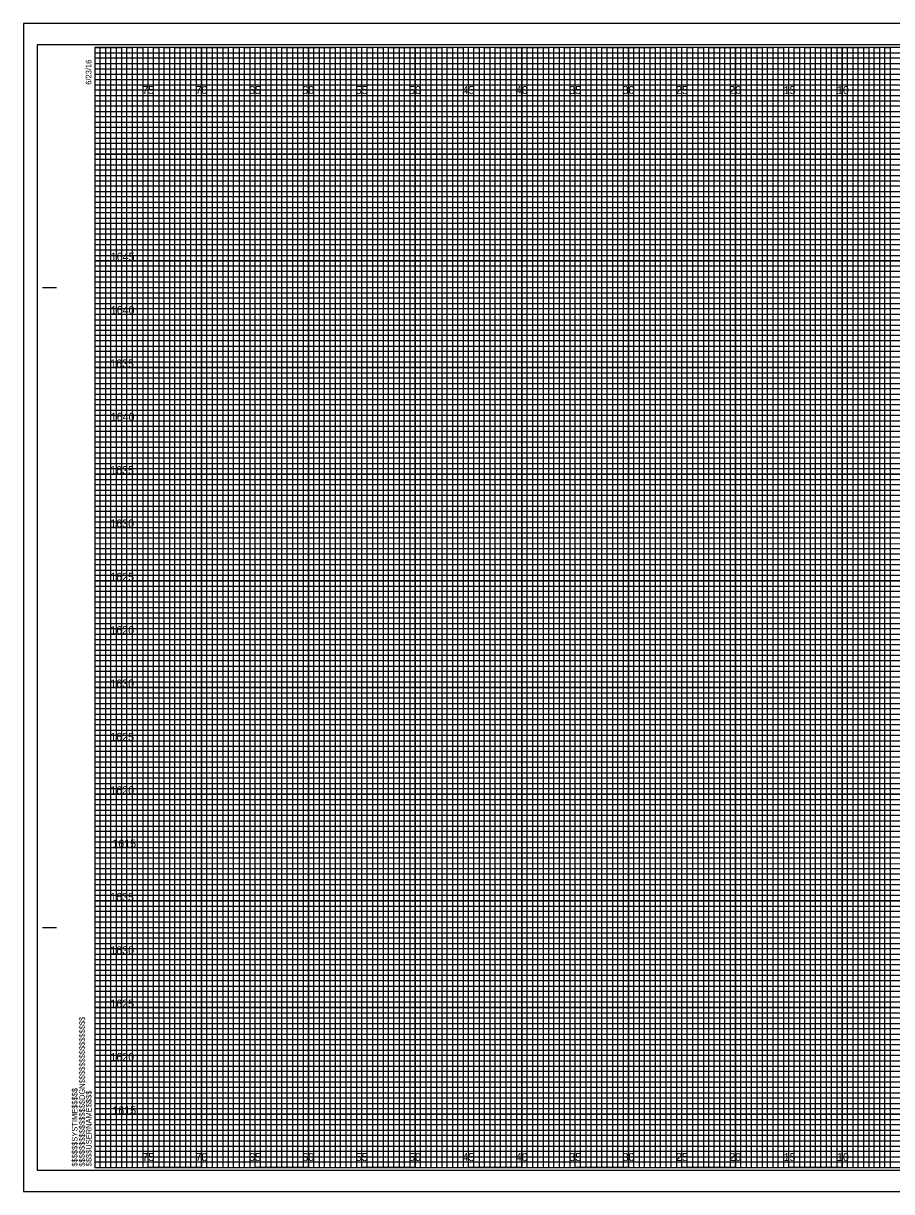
# Model space of a CAD drawing. Extents: x -7 to 162, y -2 to 107.
# Drawn here: x -6.7 to 74.6, y -2.3 to 107.3 of the extents above; entities that cross this region are included whole.
import ezdxf

# ---------------------------------------------------------------- set-up
doc = ezdxf.new("R2010")
doc.units = 0
for name, color, linetype in [('Prop XS Elevation Labels', 7, 'Continuous'), ('Prop XS Offset Labels', 7, 'Continuous'), ('Sheet Cross Section CELL', 7, 'Continuous'), ('Sheet Cross Section Grid Major CELL', 7, 'Continuous'), ('Sheet Cross Section Grid Middle CELL', 7, 'Continuous'), ('Sheet Cross Section Grid Minor 1 CELL', 7, 'Continuous'), ('Sheet Cross Section Grid Minor 2 CELL', 7, 'Continuous'), ('Sheet Cutting Line CELL', 7, 'Continuous'), ('Sheet DOT Grid CELL', 7, 'Continuous'), ('Sheet Plot Border Inside CELL', 7, 'Continuous'), ('Sheet Plot Border Outside CELL', 7, 'Continuous')]:
    doc.layers.add(name, color=color, linetype=linetype)

msp = doc.modelspace()

# ---------------------------------------------------------------- linework, layer by layer
at = {"layer": 'Sheet Cross Section CELL'}
for p, q in [((-4.9, 82.5), (-3.65, 82.5)), ((-4.85, 82.5), (-3.6, 82.5)), ((-4.9, 22.5), (-3.65, 22.5)), ((-4.85, 22.5), (-3.6, 22.5)), ((0, 0), (0, 0)), ((0, 0), (0, 0)), ((0, 0), (0, 0)), ((0, 0), (0, 0)), ((0, 0), (0, 0)), ((0, 0), (0, 0)), ((0, 0), (0, 0))]:
    msp.add_line(p, q, dxfattribs=at)
msp.add_lwpolyline([(160, 105), (0, 105), (0, 0), (160, 0)], close=True, dxfattribs=at)
at = {"layer": 'Sheet Cross Section Grid Major CELL'}
for p, q in [((5, 105), (0, 105)), ((5, 0), (5, 105)), ((15, 105), (10, 105)), ((10, 105), (10, 0)), ((15, 0), (15, 105)), ((25, 105), (20, 105)), ((20, 105), (20, 0)), ((25, 0), (25, 105)), ((35, 105), (30, 105)), ((30, 105), (30, 0)), ((35, 0), (35, 105)), ((45, 105), (40, 105)), ((40, 105), (40, 0)), ((45, 0), (45, 105)), ((55, 105), (50, 105)), ((50, 105), (50, 0)), ((55, 0), (55, 105)), ((65, 105), (60, 105)), ((60, 105), (60, 0)), ((65, 0), (65, 105)), ((75, 105), (70, 105)), ((70, 105), (70, 0)), ((10, 0), (5, 0)), ((20, 0), (15, 0)), ((30, 0), (25, 0)), ((40, 0), (35, 0)), ((50, 0), (45, 0)), ((60, 0), (55, 0)), ((70, 0), (65, 0))]:
    msp.add_line(p, q, dxfattribs=at)
for points in [[(0, 100), (160, 100), (160, 95), (0, 95)], [(0, 90), (160, 90), (160, 85), (0, 85)], [(0, 80), (160, 80), (160, 75), (0, 75)], [(0, 70), (160, 70), (160, 65), (0, 65)], [(0, 60), (160, 60), (160, 55), (0, 55)], [(0, 50), (160, 50), (160, 45), (0, 45)], [(0, 40), (160, 40), (160, 35), (0, 35)], [(0, 30), (160, 30), (160, 25), (0, 25)], [(0, 20), (160, 20), (160, 15), (0, 15)], [(0, 10), (160, 10), (160, 5), (0, 5)]]:
    msp.add_lwpolyline(points, dxfattribs=at)
at = {"layer": 'Sheet Cross Section Grid Middle CELL'}
for points in [[(0, 105), (2.5, 105), (2.5, 0), (7.5, 0), (7.5, 105), (12.5, 105), (12.5, 0), (17.5, 0), (17.5, 105), (22.5, 105), (22.5, 0), (27.5, 0), (27.5, 105), (32.5, 105), (32.5, 0), (37.5, 0), (37.5, 105), (42.5, 105), (42.5, 0), (47.5, 0), (47.5, 105), (52.5, 105), (52.5, 0), (57.5, 0), (57.5, 105), (62.5, 105), (62.5, 0), (67.5, 0), (67.5, 105), (72.5, 105), (72.5, 0), (77.5, 0)], [(0, 102.5), (137.5, 102.5)], [(0, 92.5), (160, 92.5), (160, 97.5), (0, 97.5)], [(0, 82.5), (160, 82.5), (160, 87.5), (0, 87.5)], [(0, 72.5), (160, 72.5), (160, 77.5), (0, 77.5)], [(0, 62.5), (160, 62.5), (160, 67.5), (0, 67.5)], [(0, 52.5), (160, 52.5), (160, 57.5), (0, 57.5)], [(0, 42.5), (160, 42.5), (160, 47.5), (0, 47.5)], [(0, 32.5), (160, 32.5), (160, 37.5), (0, 37.5)], [(0, 22.5), (160, 22.5), (160, 27.5), (0, 27.5)], [(0, 12.5), (160, 12.5), (160, 17.5), (0, 17.5)], [(0, 2.5), (160, 2.5), (160, 7.5), (0, 7.5)]]:
    msp.add_lwpolyline(points, dxfattribs=at)
at = {"layer": 'Sheet Cross Section Grid Minor 1 CELL'}
for p, q in [((0, 104.5), (130, 104.5)), ((130, 103.99), (0, 103.99)), ((0, 103.99), (0, 103.5)), ((0, 103.5), (130, 103.5)), ((130, 102.95), (0, 102.95)), ((0, 102.95), (0, 102)), ((0, 102), (160, 102))]:
    msp.add_line(p, q, dxfattribs=at)
for points in [[(0, 101.5), (135, 101.5), (160, 101.5), (160, 101), (0, 101)], [(0, 100.5), (160, 100.5), (160, 99.5), (0, 99.5)], [(0, 99), (160, 99), (160, 98.5), (0, 98.49)], [(0, 98), (160, 98), (160, 97), (0, 97)], [(0, 96.5), (160, 96.5), (160, 96), (0, 96)], [(0, 95.5), (160, 95.5), (160, 94.5), (0, 94.5)], [(0, 94), (160, 94), (160, 93.5), (0, 93.5)], [(0, 93), (160, 93), (160, 92), (0, 92)], [(0, 91.5), (160, 91.5), (160, 91), (0, 91)], [(0, 90.5), (160, 90.5), (160, 89.5), (0, 89.5)], [(0, 89), (160, 89), (160, 88.5), (0, 88.5)], [(0, 88), (160, 88), (160, 86.98), (160, 86.5), (160, 86), (0, 86)], [(0, 87), (160, 87), (160, 86.5), (0, 86.5)], [(0, 85.5), (160, 85.5), (160, 84.5), (0, 84.52)], [(0, 84.52), (160, 84.5), (160, 84), (0, 84)], [(0, 83.5), (160, 83.5), (160, 83), (0, 83)], [(0, 82), (160, 82), (160, 81.5), (0, 81.5)], [(0, 81), (160, 81), (160, 80.5), (0, 80.5)], [(-0.04, 79.45), (160, 79.45), (160, 78.94), (-0.04, 78.94)], [(0, 78.5), (160, 78.5), (160, 78), (0, 78)], [(0, 77), (160, 77), (160, 76.5), (0, 76.5)], [(0, 76), (160, 76), (160, 75.5), (0, 75.5)], [(0, 74.5), (160, 74.5), (160, 74), (0, 74)], [(0, 73.5), (160, 73.5), (160, 73), (0, 73)], [(0, 72), (160, 72), (160, 71.5), (0, 71.5)], [(0, 71), (160, 71), (160, 70.5), (0, 70.5)], [(0, 69.5), (160, 69.5), (160, 68.99), (0, 69)], [(0, 68.5), (160, 68.5), (160, 68), (0, 68)], [(0, 67), (160, 67), (160, 66.5), (0, 66.5)], [(0, 66), (160, 66), (160, 65.5), (0, 65.5)], [(0, 64.5), (160, 64.5), (160, 64), (0, 64)], [(0, 63.5), (160, 63.5), (160, 63), (0, 63)], [(0, 62), (160, 62), (160, 61.5), (0, 61.5)], [(0, 61), (160, 61), (160, 60.5), (0, 60.5)], [(0, 59.5), (160, 59.5), (160, 59), (0, 59)], [(0, 58.5), (160.03, 58.45), (160, 58), (0, 58)], [(0, 57), (160, 57), (160, 56.5), (0, 56.5)], [(0, 56), (160, 56), (160, 55.5), (0, 55.5)], [(0, 54.5), (160, 54.5), (160, 54), (0, 54)], [(0, 53.5), (160, 53.5), (160, 53), (0, 53)], [(0, 52), (160, 52), (160, 51.5), (0, 51.5)], [(0, 51), (160, 51), (160, 50.5), (0, 50.5)], [(0, 49.5), (160, 49.5), (160, 49), (0, 49)], [(0, 48.5), (160, 48.5), (160, 48), (0, 48)], [(0, 47), (160, 47), (160, 46.5), (0, 46.5)], [(0, 46), (160, 46), (160, 45.5), (0, 45.5)], [(0, 44.5), (160, 44.5), (160, 44), (0, 44)], [(0, 43.5), (160, 43.5), (160, 43), (0, 43)], [(0, 42), (160, 42), (160, 41.5), (0, 41.5)], [(0, 41), (160, 41), (160, 40.5), (0, 40.5)], [(0, 39.5), (160, 39.5), (160, 38.99), (0, 39)], [(0, 38.5), (160, 38.5), (160, 38), (0, 38)], [(0, 37), (160, 37), (160, 36.5), (0, 36.5)], [(0, 36), (160, 36), (160, 35.5), (0, 35.5)], [(0, 34.5), (160, 34.5), (160, 34), (0, 34)], [(0, 33.5), (160, 33.5), (160, 33), (0, 33)], [(0, 32), (160, 32), (160, 31.5), (0, 31.5)], [(0, 31), (160, 31), (160, 30.5), (0, 30.5)], [(0, 29.5), (160, 29.5), (160, 29), (0, 29)], [(0, 28.5), (160.03, 28.46), (160, 28), (0, 28)], [(0, 27), (160, 27), (160, 26.5), (0, 26.5)], [(0, 26), (160, 26), (160, 25.5), (0, 25.5)], [(0, 24.5), (160, 24.5), (160, 24), (0, 24)], [(0, 23.5), (160, 23.5), (160, 23), (0, 23)], [(0, 22), (160, 22), (160, 21.5), (0, 21.5)], [(0, 21), (160, 21), (160, 20.5), (0, 20.5)], [(0, 19.5), (160, 19.5), (160, 19), (0, 19)], [(0, 18.5), (160, 18.5), (160, 18), (0, 18)], [(0, 17), (160, 17), (160, 16.5), (0, 16.5)], [(0, 16), (160, 16), (160, 15.5), (0, 15.5)], [(0, 14.5), (160, 14.5), (160, 14), (0, 14)], [(0, 13.5), (160, 13.5), (160, 13), (0, 13)], [(0, 12), (160, 12), (160, 11.5), (0, 11.5)], [(0, 11), (160, 11), (160, 10.5), (0, 10.5)], [(0, 9.5), (160, 9.5), (160, 9), (0, 9)], [(0, 8.5), (160, 8.5), (160, 8), (0, 8)], [(0, 7), (160, 7), (160, 6.5), (0, 6.5)], [(0, 6), (160, 6), (160, 5.5), (0, 5.5)], [(0, 4.5), (160, 4.5), (160, 4), (0, 4)], [(0, 3.5), (160, 3.5), (160, 3), (0, 3)], [(0, 2), (160, 2), (160, 1.5), (0, 1.5)], [(0, 1), (160, 1), (160, 0.5), (0, 0.5)]]:
    msp.add_lwpolyline(points, dxfattribs=at)
at = {"layer": 'Sheet Cross Section Grid Minor 2 CELL'}
for points in [[(0, 0), (0.5, 0), (0.5, 105), (1, 105), (1, 0)], [(1, 0), (1.5, 0), (1.5, 105), (2, 105), (2, 0)], [(2.5, 0), (3, 0), (3, 105), (3.5, 105), (3.5, 0)], [(3.5, 0), (4, 0), (4, 105), (4.5, 105), (4.5, 0)], [(5, 0), (5.5, 0), (5.5, 105), (6, 105), (6, 0)], [(6, 0), (6.5, 0), (6.5, 105), (7, 105), (7, 0)], [(7.5, 0), (8, 0), (8, 105), (8.5, 105), (8.5, 0)], [(8.5, 0), (9, 0), (9, 105), (9.5, 105), (9.5, 0)], [(10, 0), (10.5, 0), (10.5, 105), (11, 105), (11, 0)], [(11, 0), (11.5, 0), (11.5, 105), (12, 105), (12, 0)], [(12.5, 0), (13, 0), (13, 105), (13.5, 105), (13.5, 0)], [(13.5, 0), (14, 0), (14, 105), (14.5, 105), (14.5, 0)], [(15, 0), (15.5, 0), (15.5, 105), (16, 105), (16, 0)], [(16, 0), (16.5, 0), (16.5, 105), (17, 105), (17, 0)], [(17.5, 0), (18, 0), (18, 105), (18.5, 105), (18.5, 0)], [(18.5, 0), (19, 0), (19, 105), (19.5, 105), (19.5, 0)], [(20, 0), (20.5, 0), (20.5, 105), (21, 105), (21, 0)], [(21, 0), (21.5, 0), (21.5, 105), (22, 105), (22, 0)], [(22.5, 0), (23, 0), (23, 105), (23.5, 105), (23.5, 0)], [(23.5, 0), (24, 0), (24, 105), (24.5, 105), (24.5, 0)], [(25, 0), (25.5, 0), (25.5, 105), (26, 105), (26, 0)], [(26, 0), (26.5, 0), (26.5, 105), (27, 105), (27, 0)], [(27.5, 0), (28, 0), (28, 105), (28.5, 105), (28.5, 0)], [(28.5, 0), (29, 0), (29, 105), (29.5, 105), (29.5, 0)], [(30, 0), (30.5, 0), (30.5, 105), (31, 105), (31, 0)], [(31, 0), (31.5, 0), (31.5, 105), (32, 105), (32, 0)], [(32.5, 0), (33, 0), (33, 105), (33.5, 105), (33.5, 0)], [(33.5, 0), (34, 0), (34, 105), (34.5, 105), (34.5, 0)], [(35, 0), (35.5, 0), (35.5, 105), (36, 105), (36, 0)], [(36, 0), (36.5, 0), (36.5, 105), (37, 105), (37, 0)], [(37.5, 0), (38, 0), (38, 105), (38.5, 105), (38.5, 0)], [(38.5, 0), (39, 0), (39, 105), (39.5, 105), (39.5, 0)], [(40, 0), (40.5, 0), (40.5, 105), (41, 105), (41, 0)], [(41, 0), (41.5, 0), (41.5, 105), (42, 105), (42, 0)], [(42.5, 0), (43, 0), (43, 105), (43.5, 105), (43.5, 0)], [(43.5, 0), (44, 0), (44, 105), (44.5, 105), (44.5, 0)], [(45, 0), (45.5, 0), (45.5, 105), (46, 105), (46, 0)], [(46, 0), (46.5, 0), (46.5, 105), (47, 105), (47, 0)], [(47.5, 0), (48, 0), (48, 105), (48.5, 105), (48.5, 0)], [(48.5, 0), (49, 0), (49, 105), (49.5, 105), (49.5, 0)], [(50, 0), (50.5, 0), (50.5, 105), (51, 105), (51, 0)], [(51, 0), (51.5, 0), (51.5, 105), (52, 105), (52, 0)], [(52.5, 0), (53, 0), (53, 105), (53.5, 105), (53.5, 0)], [(53.5, 0), (54, 0), (54, 105), (54.5, 105), (54.5, 0)], [(55, 0), (55.5, 0), (55.5, 105), (56, 105), (56, 0)], [(56, 0), (56.5, 0), (56.5, 105), (57, 105), (57, 0)], [(57.5, 0), (58, 0), (58, 105), (58.5, 105), (58.5, 0)], [(58.5, 0), (59, 0), (59, 105), (59.5, 105), (59.5, 0)], [(60, 0), (60.5, 0), (60.5, 105), (61, 105), (61, 0)], [(61, 0), (61.5, 0), (61.5, 105), (62, 105), (62, 0)], [(62.5, 0), (63, 0), (63, 105), (63.5, 105), (63.5, 0)], [(63.5, 0), (64, 0), (64, 105), (64.5, 105), (64.5, 0)], [(65, 0), (65.5, 0), (65.5, 105), (66, 105), (66, 0)], [(66, 0), (66.5, 0), (66.5, 105), (67, 105), (67, 0)], [(67.5, 0), (68, 0), (68, 105), (68.5, 105), (68.5, 0)], [(68.5, 0), (69, 0), (69, 105), (69.5, 105), (69.5, 0)], [(70, 0), (70.5, 0), (70.5, 105), (71, 105), (71, 0)], [(71, 0), (71.5, 0), (71.5, 105), (72, 105), (72, 0)], [(72.5, 0), (73, 0), (73, 105), (73.5, 105), (73.5, 0)], [(73.5, 0), (74, 0), (74, 105), (74.5, 105), (74.5, 0)]]:
    msp.add_lwpolyline(points, dxfattribs=at)
at = {"layer": 'Sheet Cutting Line CELL'}
for p, q in [((161.65, 107.25), (-6.7, 107.25)), ((-6.7, 107.25), (-6.7, -2.25)), ((-6.7, -2.25), (161.65, -2.25))]:
    msp.add_line(p, q, dxfattribs=at)
at = {"layer": 'Sheet DOT Grid CELL'}
for p, q in [((5, 0), (5, 105)), ((10, 0), (10, 105)), ((15, 0), (15, 105)), ((20, 0), (20, 105)), ((25, 0), (25, 105)), ((30, 0), (30, 105)), ((35, 0), (35, 105)), ((40, 0), (40, 105)), ((45, 0), (45, 105)), ((50, 0), (50, 105)), ((55, 0), (55, 105)), ((60, 0), (60, 105)), ((65, 0), (65, 105)), ((70, 0), (70, 105)), ((0, 100), (160, 100)), ((0, 95), (160, 95)), ((0, 90), (160, 90)), ((0, 85), (160, 85)), ((0, 80), (160, 80)), ((0, 75), (160, 75)), ((0, 70), (160, 70)), ((0, 65), (160, 65)), ((0, 60), (160, 60)), ((0, 55), (160, 55)), ((0, 50), (160, 50)), ((0, 45), (160, 45)), ((0, 40), (160, 40)), ((0, 35), (160, 35)), ((0, 30), (160, 30)), ((0, 25), (160, 25)), ((0, 20), (160, 20)), ((0, 15), (160, 15)), ((0, 10), (160, 10)), ((0, 5), (160, 5))]:
    msp.add_line(p, q, dxfattribs=at)
at = {"layer": 'Sheet Plot Border Inside CELL'}
msp.add_lwpolyline([(-5.4, -0.25), (161.2, -0.25), (161.2, 105.25), (-5.4, 105.25)], close=True, dxfattribs=at)
at = {"layer": 'Sheet Plot Border Outside CELL'}
msp.add_lwpolyline([(-6.7, -2.25), (161.65, -2.25), (161.65, 107.25), (-6.7, 107.25)], close=True, dxfattribs=at)

# ---------------------------------------------------------------- texts
at = {"layer": 'Prop XS Elevation Labels'}
for s, p in [('1645', (1.48, 85)), ('1640', (1.48, 80)), ('1635', (1.43, 75)), ('1640', (1.48, 70)), ('1635', (1.43, 65)), ('1630', (1.44, 60)), ('1625', (1.44, 55)), ('1620', (1.45, 50)), ('1630', (1.44, 45)), ('1625', (1.44, 40)), ('1620', (1.45, 35)), ('1615', (1.63, 30)), ('1635', (1.43, 25)), ('1630', (1.44, 20)), ('1625', (1.44, 15)), ('1620', (1.45, 10)), ('1615', (1.63, 5))]:
    msp.add_text(s, height=0.75, dxfattribs=at).set_placement(p)
at = {"layer": 'Prop XS Offset Labels'}
for s, p in [('75', (4.44, 100.62)), ('70', (9.43, 100.62)), ('65', (14.44, 100.62)), ('60', (19.43, 100.62)), ('55', (24.44, 100.62)), ('50', (29.43, 100.62)), ('45', (34.44, 100.62)), ('40', (39.43, 100.62)), ('35', (44.44, 100.62)), ('30', (49.43, 100.62)), ('25', (54.44, 100.62)), ('20', (59.43, 100.62)), ('15', (64.53, 100.62)), ('10', (69.52, 100.62)), ('75', (4.44, 0.62)), ('70', (9.43, 0.62)), ('65', (14.44, 0.62)), ('60', (19.43, 0.62)), ('55', (24.44, 0.62)), ('50', (29.43, 0.62)), ('45', (34.44, 0.62)), ('40', (39.43, 0.62)), ('35', (44.44, 0.62)), ('30', (49.43, 0.62)), ('25', (54.44, 0.62)), ('20', (59.43, 0.62)), ('15', (64.53, 0.62)), ('10', (69.52, 0.62))]:
    msp.add_text(s, height=0.75, dxfattribs=at).set_placement(p)
at = {"layer": 'Sheet Cross Section CELL'}
for s, p in [('6/23/16', (-0.33, 101.5)), ('$$$$$$$$$$$$$$$$DGN$$$$$$$$$$$$$$$$', (-0.94, 0.09)), ('$$$$$$SYSTIME$$$$$', (-1.63, 0.09)), ('$$$$USERNAME$$$$', (-0.31, 0.12))]:
    msp.add_text(s, height=0.525, rotation=90, dxfattribs=at).set_placement(p)

doc.saveas('drawing.dxf')
